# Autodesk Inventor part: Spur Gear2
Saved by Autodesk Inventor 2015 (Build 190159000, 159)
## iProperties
Created: 2014-06
Part Number: Spur Gear2
Material: Steel
Document SubType Name: Modeling
Designer: User
Categories: <?xml version="1.0" encoding="UTF-16"?> <MemberInstance><Categories><FamilyTemplate><FamilyTemplateParameter ValueType="xs:double" Id="1" ObjectReferenceKey="da
Density: 1 g/cm^3
Appearance: Steel
CustomPartVersion: 1
Author: User
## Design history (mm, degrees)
sketch "Sketch1"
  geometry: C1 r 9.449 at (0, 0)
  constraints: 1 centre point
  dimensions: "d0" = 18.89761 diameter of C1 (= da_da)
extrude "Extrusion1" new body sketch "Sketch1" distance "d1" = 4 (= da_b); taper "d2" = 0 deg
workplane "Work Plane2"
sketch "Sketch2"
  geometry: C1 r 9.449 at (0, 0) reference; C2 r 8.75 at (0, 0)
  constraints: 1 centre point, 1 coincident
  dimensions: "d3" = 17.5 diameter of C2 (= da_dw)
feature "Pitch Diameter" sketch "Sketch2" dims "d4" = 10, "d5" = 0
workplane "Work Plane8"
workplane "Work Plane9"
feature "Spur Gear" dims "da_b" = 4, "da_d" = 17.36192, "da_aw" = 17.5, "da_da" = 18.89761, "da_df" = 15.75239, "da_dw" = 17.5, angle "da_beta" = 40 deg, "da_lefttooth" = 0, "da_righttooth" = 10
body "Solid1"
body "Srf1"
other parameters: "d16" = 17.5 (= da_aw), "d17" = 0, "d34" = 1.65347 (computed from da_z), "d39" = 0, "d41" = 0, "d43" = 17.5 (= da_aw), "d46" = 17.5 (= da_aw), "d47" = 0, "d48" = 0
